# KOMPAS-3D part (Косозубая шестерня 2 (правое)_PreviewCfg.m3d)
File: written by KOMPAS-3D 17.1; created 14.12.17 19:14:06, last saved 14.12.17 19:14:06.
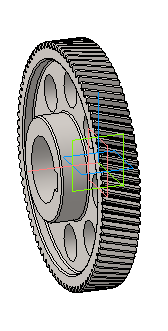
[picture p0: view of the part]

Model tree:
1. Операция без истории:1  (labels: Косозубая шестерня 2 (правое)_PreviewCfg)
